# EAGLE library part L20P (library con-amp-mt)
AMP MT CONNECTOR
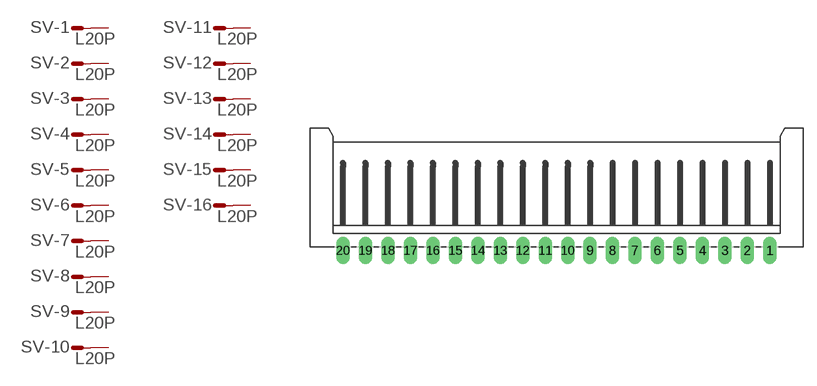
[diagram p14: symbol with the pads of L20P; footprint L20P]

Designator prefix SV; gates -1=M -2=M -3=M -4=M -5=M -6=M -7=M -8=M -9=M -10=M -11=M -12=M -13=M -14=M -15=M -16=M -17=M -18=M -19=M -20=M

## L20P (OC_FARNELL: unknown; OC_NEWARK: unknown)  [L20P]
1  -1:S  pas
2  -2:S  pas
3  -3:S  pas
4  -4:S  pas
5  -5:S  pas
6  -6:S  pas
7  -7:S  pas
8  -8:S  pas
9  -9:S  pas
10  -10:S  pas
11  -11:S  pas
12  -12:S  pas
13  -13:S  pas
14  -14:S  pas
15  -15:S  pas
16  -16:S  pas
17  -17:S  pas
18  -18:S  pas
19  -19:S  pas
20  -20:S  pas

## Footprint L20P (pad centres in mm)
AMP MT CONNECTOR
drill 1.016 long: 1 23.75,-6.25; 2 21.25,-6.25; 3 18.75,-6.25; 4 16.25,-6.25; 5 13.75,-6.25; 6 11.25,-6.25; 7 8.75,-6.25; 8 6.25,-6.25; 9 3.75,-6.25; 10 1.25,-6.25; 11 -1.25,-6.25; 12 -3.75,-6.25; 13 -6.25,-6.25; 14 -8.75,-6.25; 15 -11.25,-6.25; 16 -13.74,-6.25; 17 -16.255,-6.25; 18 -18.744,-6.25; 19 -21.259,-6.25; 20 -23.748,-6.25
